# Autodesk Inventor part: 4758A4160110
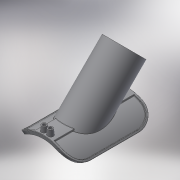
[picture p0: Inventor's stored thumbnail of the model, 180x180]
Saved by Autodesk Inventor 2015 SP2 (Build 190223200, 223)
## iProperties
Created: 2017-08
Part Number: 4758A4160110
Material: Generic
Description: PLASSON WASTEWATER SADDLE 45 INLET 160-200 X 110
Document SubType Name: Modeling
Designer: Кирилл
Density: 1 g/cm^3
Appearance: Default
Author: Кирилл
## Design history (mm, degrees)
derived "4758A4.ipt"
feature "Solid1::4758A4.ipt"
feature "Solid2::4758A4.ipt"
tag "TaggingFeature1"
body "Solid1"
other parameters: "d1" = 182, "d3" = 255, "d4" = 0, "d5" = 54.6, "d6" = 6, "d7" = 30 deg, "d8" = 15 deg, "d10" = 0, "d12" = 15, "d13" = 15, "d14" = 114.75, "d18" = 5 deg, "d19" = 4, "d20" = 4, "d23" = 14, "d24" = 0, "d25" = 4, "d26" = 0, "d27" = 45 deg, "d30" = 158, "d32" = 93.5, "d35" = 0, "d37" = 0, "d38" = 1, "d39" = 2, "d40" = 126, "d41" = 15, "d42" = 114.75, "d43" = 18.7, "d44" = 9.35, "d46" = 5 deg, "d47" = 4, "d49" = 4, "d51" = 14, "d52" = 0, "d53" = 3, "d54" = 0, "B_" = 182, "H_" = 158, "L_" = 255
